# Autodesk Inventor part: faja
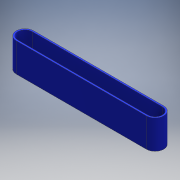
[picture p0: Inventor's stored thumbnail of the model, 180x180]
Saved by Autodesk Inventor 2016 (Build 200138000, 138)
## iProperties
Created: 2016-06
Part Number: faja
Material: Genérico
Document SubType Name: Modeling
Designer: adm
Density: 1 g/cm^3
Appearance: Valor por defecto
Author: adm
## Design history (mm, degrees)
sketch "Boceto1"
  geometry: L1 (-180, 15)-(270, 15); L2 (270, -35)-(-180, -35); L3 (270, 20)-(-180, 20); L4 (-180, -40)-(270, -40); A1 r 25 centre (-180, -10) between (-180, 15) and (-180, -35); A2 r 25 centre (270, -10) between (270, -35) and (270, 15); A3 r 30 centre (-180, -10) between (-180, 20) and (-180, -40); A4 r 30 centre (270, -10) between (270, -40) and (270, 20); 1 further point
  constraints: 8 end point, 8 point on circle, 4 centre point, 3 tangent, 3 other
  dimensions: "d0" = 50 diameter of A1; "d2" = 50 diameter of A2; "d4" = 5 distance between parallel lines of L1 L3; "d8" = 450 distance of A2.centre A1.centre
extrude "Extrusión1" new body sketch "Boceto1" distance "d5" = 100; taper "d6" = 0 deg
node "Sólido1"
